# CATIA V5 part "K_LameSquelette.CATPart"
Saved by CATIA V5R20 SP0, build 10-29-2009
Part number: Lame(Squelette)
Publications: "Point.1", "Point.2", "Plan.1", "Droite.1", "Droite.2", "Droite.3", "Distance_Inter_Pivot"
Bounding box of the stored display mesh (mm): x -7.5 to -7.5, y 7 to 193, z -27 to -7
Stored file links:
  G:\Khaled_CFAO_2011\SIL\SIL_GR1\mneves\Khaled\CAD_CATIA_Modifie\K_LameSquelette.CATPart
  G:\Khaled_CFAO_2011\SIL\SIL_GR1\mneves\Khaled\CAD_CATIA_Modifie\K_SquePince_A_Bois.CATProduct
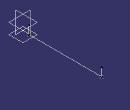
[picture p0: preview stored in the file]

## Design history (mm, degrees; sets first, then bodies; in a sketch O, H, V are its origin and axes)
External parameters (linked from other documents)
  External.Distance_Inter_Pivot = 200 mm
Set1
  Point1: linked copy from another document
  Point2: linked copy from another document
  Plane1: linked copy from another document
Set2
  Line1: type PtPt, FirstPoint Point1, SecondPoint Point2
  Line2: type Normal, RefPoint Point1, RefSkin Plane1, Start 0, End 20 {= External.Distance_Inter_Pivot /10}
  Line3: type Normal, RefPoint Point2, RefSkin Plane1, Start 0, End 20 {= External.Distance_Inter_Pivot /10}
Body1 (main body)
